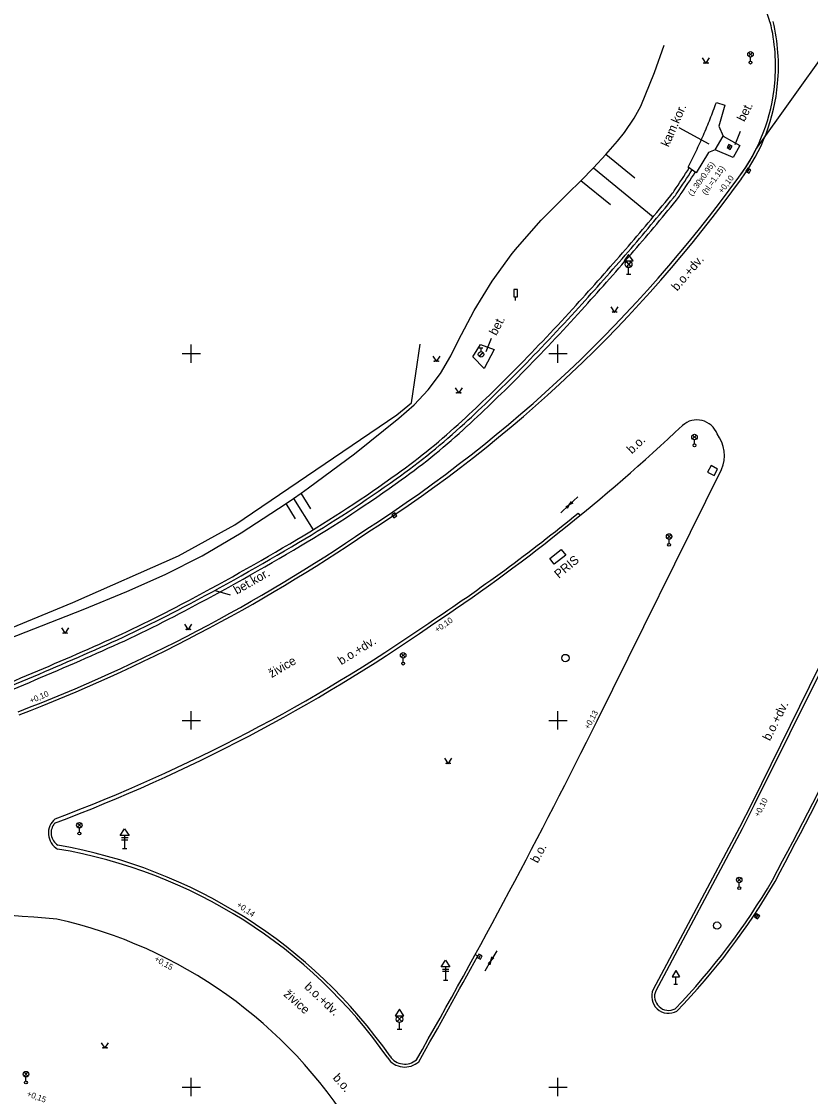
# Model space of a CAD drawing. Extents: x -599151 to -598424, y -1163476 to -1161924.
# Drawn here: x -598936.6 to -598882.8, y -1163175.6 to -1163102.4 of the extents above; entities that cross this region are included whole.
import ezdxf

# ---------------------------------------------------------------- set-up
doc = ezdxf.new("R2010")
doc.units = 0
for name, color, linetype in [('Vrstva 10', 7, 'Continuous'), ('Vrstva 14', 7, 'Continuous'), ('Vrstva 15', 7, 'Continuous'), ('Vrstva 19', 7, 'Continuous'), ('Vrstva 23', 7, 'Continuous'), ('Vrstva 24', 7, 'Continuous'), ('Vrstva 25', 7, 'Continuous'), ('Vrstva 29', 7, 'Continuous'), ('Vrstva 41', 7, 'Continuous'), ('Vrstva 44', 7, 'Continuous'), ('Vrstva 49', 7, 'Continuous'), ('Vrstva 50', 7, 'Continuous'), ('Vrstva 62', 7, 'Continuous'), ('Vrstva 63', 7, 'Continuous'), ('Vrstva 7', 7, 'Continuous')]:
    doc.layers.add(name, color=color, linetype=linetype)

msp = doc.modelspace()

# ---------------------------------------------------------------- linework, layer by layer
at = {"layer": 'Vrstva 10'}
msp.add_lwpolyline([(-598970.37, -1163152.041), (-598959.99, -1163150.901), (-598957.62, -1163150.501), (-598951.79, -1163148.951), (-598942, -1163145.641), (-598933.08, -1163141.961), (-598925.88, -1163138.781), (-598922.03, -1163136.681), (-598910.98, -1163129.171), (-598909.98, -1163128.361), (-598909.39, -1163124.361)], dxfattribs=at)
at = {"layer": 'Vrstva 14'}
for points in [[(-598890.156, -1163104.838), (-598889.906, -1163105.213), (-598889.656, -1163104.838)], [(-598896.392, -1163121.814), (-598896.142, -1163122.189), (-598895.892, -1163121.814)], [(-598908.54, -1163125.165), (-598908.29, -1163125.54), (-598908.04, -1163125.165)], [(-598907.013, -1163127.327), (-598906.763, -1163127.702), (-598906.513, -1163127.327)], [(-598933.85, -1163143.699), (-598933.6, -1163144.074), (-598933.35, -1163143.699)], [(-598925.45, -1163143.445), (-598925.2, -1163143.82), (-598924.95, -1163143.445)], [(-598907.73, -1163152.577), (-598907.48, -1163152.952), (-598907.23, -1163152.577)], [(-598931.131, -1163171.975), (-598930.881, -1163172.35), (-598930.631, -1163171.975)]]:
    msp.add_lwpolyline(points, dxfattribs=at)
for centre in [(-598890.031, -1163105.188), (-598889.781, -1163105.188), (-598896.267, -1163122.164), (-598896.017, -1163122.164), (-598908.415, -1163125.515), (-598908.165, -1163125.515), (-598906.888, -1163127.677), (-598906.638, -1163127.677), (-598933.725, -1163144.049), (-598933.475, -1163144.049), (-598925.325, -1163143.795), (-598925.075, -1163143.795), (-598907.605, -1163152.927), (-598907.355, -1163152.927), (-598931.006, -1163172.325), (-598930.756, -1163172.325)]:
    msp.add_circle(centre, 0.025, dxfattribs=at)
at = {"layer": 'Vrstva 15'}
msp.add_line((-598902.89, -1163121.39), (-598902.89, -1163121.14), dxfattribs=at)
msp.add_lwpolyline([(-598903.015, -1163121.14), (-598902.765, -1163121.14), (-598902.765, -1163120.64), (-598903.015, -1163120.64)], close=True, dxfattribs=at)
at = {"layer": 'Vrstva 19'}
for p, q in [((-598891.97, -1163167.057), (-598892.22, -1163167.49)), ((-598892.22, -1163167.49), (-598891.72, -1163167.49)), ((-598891.97, -1163167.057), (-598891.72, -1163167.49)), ((-598891.97, -1163167.99), (-598891.97, -1163167.49)), ((-598892.095, -1163167.99), (-598891.845, -1163167.99))]:
    msp.add_line(p, q, dxfattribs=at)
at = {"layer": 'Vrstva 23'}
for p, q in [((-598889.563, -1163132.632), (-598889.798, -1163133.073)), ((-598889.798, -1163133.073), (-598889.357, -1163133.308)), ((-598889.122, -1163132.867), (-598889.563, -1163132.632)), ((-598889.357, -1163133.308), (-598889.122, -1163132.867))]:
    msp.add_line(p, q, dxfattribs=at)
at = {"layer": 'Vrstva 24'}
for p, q in [((-598905.387, -1163125.166), (-598905.092, -1163124.934)), ((-598905.365, -1163124.612), (-598905.115, -1163124.612)), ((-598905.24, -1163124.862), (-598905.24, -1163124.612))]:
    msp.add_line(p, q, dxfattribs=at)
msp.add_circle((-598905.24, -1163125.05), 0.188, dxfattribs=at)
at = {"layer": 'Vrstva 25'}
for p, q in [((-598888.365, -1163111.018), (-598888.235, -1163110.804)), ((-598887.075, -1163112.627), (-598886.945, -1163112.413)), ((-598911.264, -1163136.09), (-598911.056, -1163135.95)), ((-598886.491, -1163163.463), (-598886.349, -1163163.257)), ((-598905.399, -1163166.22), (-598905.281, -1163166))]:
    msp.add_line(p, q, dxfattribs=at)
for points in [[(-598888.258, -1163111.083), (-598888.128, -1163110.869), (-598888.342, -1163110.739), (-598888.472, -1163110.953)], [(-598886.968, -1163112.692), (-598886.838, -1163112.478), (-598887.052, -1163112.348), (-598887.182, -1163112.562)], [(-598911.194, -1163136.194), (-598910.986, -1163136.054), (-598911.126, -1163135.846), (-598911.334, -1163135.986)], [(-598886.387, -1163163.534), (-598886.246, -1163163.327), (-598886.453, -1163163.186), (-598886.594, -1163163.393)], [(-598905.288, -1163166.279), (-598905.171, -1163166.058), (-598905.392, -1163165.941), (-598905.509, -1163166.162)]]:
    msp.add_lwpolyline(points, close=True, dxfattribs=at)
for centre in [(-598899.49, -1163145.75), (-598889.15, -1163163.99)]:
    msp.add_circle(centre, 0.25, dxfattribs=at)
at = {"layer": 'Vrstva 29'}
for p, q in [((-598887.002, -1163104.73), (-598886.738, -1163104.466)), ((-598886.734, -1163104.729), (-598886.998, -1163104.464)), ((-598886.87, -1163105.061), (-598886.87, -1163104.786)), ((-598890.822, -1163130.819), (-598890.558, -1163130.555)), ((-598890.554, -1163130.818), (-598890.818, -1163130.553)), ((-598890.69, -1163131.15), (-598890.69, -1163130.875)), ((-598892.552, -1163137.599), (-598892.288, -1163137.335)), ((-598892.284, -1163137.598), (-598892.548, -1163137.333)), ((-598892.42, -1163137.93), (-598892.42, -1163137.655)), ((-598910.682, -1163145.699), (-598910.418, -1163145.435)), ((-598910.414, -1163145.698), (-598910.678, -1163145.433)), ((-598910.55, -1163146.03), (-598910.55, -1163145.755)), ((-598932.762, -1163157.279), (-598932.498, -1163157.015)), ((-598932.494, -1163157.278), (-598932.758, -1163157.013)), ((-598932.63, -1163157.61), (-598932.63, -1163157.335)), ((-598887.772, -1163161.009), (-598887.508, -1163160.745)), ((-598887.504, -1163161.008), (-598887.768, -1163160.743)), ((-598887.64, -1163161.34), (-598887.64, -1163161.065)), ((-598936.402, -1163174.249), (-598936.138, -1163173.985)), ((-598936.134, -1163174.248), (-598936.398, -1163173.983)), ((-598936.27, -1163174.58), (-598936.27, -1163174.305))]:
    msp.add_line(p, q, dxfattribs=at)
msp.add_lwpolyline([(-598900.557, -1163138.964), (-598899.773, -1163138.344), (-598899.463, -1163138.736), (-598900.247, -1163139.356)], close=True, dxfattribs=at)
for centre, radius in [((-598886.87, -1163104.599), 0.188), ((-598886.87, -1163105.161), 0.1), ((-598890.69, -1163130.688), 0.188), ((-598890.69, -1163131.25), 0.1), ((-598892.42, -1163137.468), 0.188), ((-598892.42, -1163138.03), 0.1), ((-598910.55, -1163145.568), 0.188), ((-598910.55, -1163146.13), 0.1), ((-598932.63, -1163157.147), 0.188), ((-598932.63, -1163157.71), 0.1), ((-598887.64, -1163160.877), 0.188), ((-598887.64, -1163161.44), 0.1), ((-598936.27, -1163174.117), 0.188), ((-598936.27, -1163174.68), 0.1)]:
    msp.add_circle(centre, radius, dxfattribs=at)
at = {"layer": 'Vrstva 41'}
for points in [[(-598895.941, -1163110.509), (-598895.46, -1163109.92), (-598894.795, -1163108.961), (-598894.357, -1163108.125), (-598893.411, -1163105.847), (-598892.76, -1163103.98)], [(-598896.74, -1163111.437), (-598895.941, -1163110.509)], [(-598897.569, -1163112.342), (-598896.74, -1163111.437)], [(-598894.76, -1163113.045), (-598896.74, -1163111.437)], [(-598898.429, -1163113.222), (-598897.569, -1163112.342)], [(-598897.569, -1163112.342), (-598893.497, -1163115.665)], [(-598899.32, -1163114.077), (-598898.429, -1163113.222)], [(-598896.425, -1163114.865), (-598898.429, -1163113.222)], [(-598917.004, -1163134.158), (-598913.879, -1163131.837), (-598910.852, -1163129.39), (-598909.8, -1163128.49), (-598908.839, -1163127.472), (-598908, -1163126.352), (-598907.295, -1163125.143), (-598906.811, -1163124.132), (-598905.714, -1163122.062), (-598904.478, -1163120.071), (-598903.11, -1163118.17), (-598902.765, -1163117.743), (-598901.152, -1163115.903), (-598899.32, -1163114.077)], [(-598918.019, -1163134.87), (-598917.51, -1163134.515)], [(-598917.51, -1163134.515), (-598917.004, -1163134.158)], [(-598916.851, -1163135.582), (-598917.51, -1163134.515)], [(-598919.042, -1163135.568), (-598918.53, -1163135.221)], [(-598918.53, -1163135.221), (-598918.019, -1163134.87)], [(-598917.889, -1163136.26), (-598918.53, -1163135.221)], [(-598918.019, -1163134.87), (-598916.697, -1163137.01)], [(-598962.571, -1163152.267), (-598959.703, -1163151.72), (-598958.21, -1163151.37), (-598953.982, -1163150.231), (-598949.798, -1163148.938), (-598945.902, -1163147.581), (-598939.112, -1163145.084), (-598932.379, -1163142.438), (-598929.387, -1163141.206), (-598926.789, -1163140.066), (-598924.26, -1163138.782), (-598921.599, -1163137.228), (-598919.042, -1163135.568)]]:
    msp.add_lwpolyline(points, dxfattribs=at)
for centre, radius, start, end in [((-598959.289, -1163068.731), 81.228, 326.0972, 327.41255), ((-598895.702, -1163111.464), 4.617, 320.74636, 326.0972), ((-599028.927, -1163002.6), 176.664, 319.19091, 320.74636), ((-599044.871, -1162988.833), 197.728, 317.72064, 319.19091), ((-599007.526, -1163022.79), 147.253, 315.40117, 317.72064), ((-598980.944, -1163049.001), 109.922, 312.71655, 315.40117), ((-598938.242, -1163095.251), 46.969, 305.39357, 312.71655), ((-598966.367, -1163056.112), 95.165, 300.77255, 305.54898), ((-599006.454, -1162988.791), 173.517, 297.79088, 300.77256), ((-598969.509, -1163058.89), 94.279, 293.74558, 297.79088), ((-599065.283, -1162841.183), 332.12, 292.5952, 293.74558)]:
    msp.add_arc(centre, radius, start, end, dxfattribs=at)
at = {"layer": 'Vrstva 44'}
for p, q in [((-598895.03, -1163118.74), (-598895.33, -1163119.084)), ((-598895.33, -1163118.74), (-598895.03, -1163119.084)), ((-598895.18, -1163119.59), (-598895.18, -1163119.14)), ((-598895.33, -1163119.59), (-598895.03, -1163119.59)), ((-598929.76, -1163157.99), (-598929.312, -1163157.99)), ((-598929.54, -1163157.84), (-598929.54, -1163158.74)), ((-598929.76, -1163158.14), (-598929.317, -1163158.14)), ((-598929.69, -1163158.74), (-598929.39, -1163158.74)), ((-598907.66, -1163166.8), (-598907.66, -1163167.7)), ((-598907.88, -1163166.95), (-598907.432, -1163166.95)), ((-598907.88, -1163167.1), (-598907.437, -1163167.1)), ((-598907.81, -1163167.7), (-598907.51, -1163167.7)), ((-598910.65, -1163170.19), (-598910.95, -1163170.534)), ((-598910.95, -1163170.19), (-598910.65, -1163170.534)), ((-598910.95, -1163171.04), (-598910.65, -1163171.04)), ((-598910.8, -1163171.04), (-598910.8, -1163170.59))]:
    msp.add_line(p, q, dxfattribs=at)
for points in [[(-598895.48, -1163118.684), (-598894.88, -1163118.684), (-598895.18, -1163118.234), (-598895.48, -1163118.684)], [(-598911.1, -1163170.134), (-598910.5, -1163170.134), (-598910.8, -1163169.684), (-598911.1, -1163170.134)]]:
    msp.add_lwpolyline(points, dxfattribs=at)
for points in [[(-598929.84, -1163157.845), (-598929.54, -1163157.39), (-598929.24, -1163157.845)], [(-598907.96, -1163166.805), (-598907.66, -1163166.35), (-598907.36, -1163166.805)]]:
    msp.add_lwpolyline(points, close=True, dxfattribs=at)
for centre in [(-598895.18, -1163118.912), (-598910.8, -1163170.362)]:
    msp.add_circle(centre, 0.228, dxfattribs=at)
at = {"layer": 'Vrstva 49'}
for p, q in [((-598889.691, -1163110.717), (-598891.735, -1163109.609)), ((-598899.8, -1163135.862), (-598899.224, -1163135.318)), ((-598899.469, -1163135.451), (-598899.224, -1163135.318)), ((-598899.224, -1163135.318), (-598899.37, -1163135.557)), ((-598898.648, -1163134.773), (-598899.224, -1163135.318)), ((-598899.224, -1163135.318), (-598899.078, -1163135.079)), ((-598898.979, -1163135.184), (-598899.224, -1163135.318)), ((-598923.374, -1163141.158), (-598922.337, -1163141.446)), ((-598904.169, -1163165.7), (-598904.568, -1163166.385)), ((-598904.568, -1163166.385), (-598904.496, -1163166.114)), ((-598904.967, -1163167.069), (-598904.568, -1163166.385)), ((-598904.766, -1163166.581), (-598904.568, -1163166.385)), ((-598904.568, -1163166.385), (-598904.641, -1163166.655)), ((-598904.371, -1163166.188), (-598904.568, -1163166.385))]:
    msp.add_line(p, q, dxfattribs=at)
for points in [[(-598887.909, -1163110.739), (-598887.547, -1163109.835)], [(-598904.89, -1163124.851), (-598904.528, -1163123.947)]]:
    msp.add_lwpolyline(points, dxfattribs=at)
at = {"layer": 'Vrstva 62'}
for p, q in [((-598925.625, -1163125), (-598924.375, -1163125)), ((-598925, -1163125.625), (-598925, -1163124.375)), ((-598900.625, -1163125), (-598899.375, -1163125)), ((-598900, -1163125.625), (-598900, -1163124.375)), ((-598925.625, -1163150), (-598924.375, -1163150)), ((-598925, -1163150.625), (-598925, -1163149.375)), ((-598900.625, -1163150), (-598899.375, -1163150)), ((-598900, -1163150.625), (-598900, -1163149.375)), ((-598925, -1163175.625), (-598925, -1163174.375)), ((-598900, -1163175.625), (-598900, -1163174.375)), ((-598925.625, -1163175), (-598924.375, -1163175)), ((-598900.625, -1163175), (-598899.375, -1163175))]:
    msp.add_line(p, q, dxfattribs=at)
at = {"layer": 'Vrstva 63'}
for points in [[(-598886.501, -1163111.085), (-598879.25, -1163100.96)], [(-598897.33, -1163150.03), (-598888.84, -1163132.9)], [(-598875.4, -1163136.75), (-598879.4, -1163141.23), (-598886.61, -1163155.75), (-598887.45, -1163157.39), (-598893.33, -1163168.43)]]:
    msp.add_lwpolyline(points, dxfattribs=at)
for centre, radius, start, end in [((-598897.754, -1163105.453), 12.584, 323.25937, 333.41058), ((-598964.192, -1163057.404), 94.575, 302.69951, 324.01014), ((-598980.673, -1163035.451), 129.886, 303.6608, 313.35722), ((-598890.523, -1163130.984), 1.467, 20.52491, 131.74706), ((-598891.138, -1163131.958), 2.483, 337.71712, 36.82302), ((-598977.73, -1163042.484), 114.492, 290.94636, 304.36727), ((-599361.191, -1162908.944), 538.407, 332.0989, 334.61954), ((-598976.086, -1163046.255), 118.372, 290.66391, 304.71172), ((-599302.271, -1162948.994), 452.098, 330.27808, 333.59753), ((-598933.553, -1163157.663), 1.002, 139.43568, 237.62805), ((-598940.082, -1163192.962), 34.969, 35.00883, 80.13394), ((-598925.305, -1163137.553), 46.254, 316.04041, 329.69893), ((-598944.061, -1163271.589), 108.492, 84.76397, 98.10136), ((-598941.11, -1163194.732), 31.947, 31.6672, 77.43438), ((-598892.453, -1163168.812), 0.957, 156.4477, 297.59501), ((-598910.439, -1163172.227), 1.206, 213.90675, 310.8201)]:
    msp.add_arc(centre, radius, start, end, dxfattribs=at)
at = {"layer": 'Vrstva 7'}
for p, q in [((-598889.28, -1163111.111), (-598888.74, -1163110.171)), ((-598897.33, -1163150.03), (-598888.84, -1163132.9)), ((-598898.627, -1163135.885), (-598898.5, -1163136.04)), ((-598905.632, -1163165.95), (-598905.456, -1163166.046))]:
    msp.add_line(p, q, dxfattribs=at)
for points in [[(-598889.2, -1163107.881), (-598888.63, -1163108.061), (-598889.04, -1163109.491), (-598888.74, -1163110.171), (-598887.6, -1163110.811), (-598888.05, -1163111.641), (-598889.28, -1163111.111), (-598889.73, -1163111.281), (-598890.57, -1163112.681), (-598891.12, -1163112.281)], [(-598905.03, -1163126.021), (-598905.81, -1163125.211), (-598905.28, -1163124.371), (-598904.35, -1163124.711), (-598905.03, -1163126.021)], [(-598879.61, -1163141.11), (-598886.789, -1163155.66), (-598887.627, -1163157.297), (-598893.508, -1163168.337)], [(-598879.4, -1163141.23), (-598886.61, -1163155.75), (-598887.45, -1163157.39), (-598893.33, -1163168.43)]]:
    msp.add_lwpolyline(points, dxfattribs=at)
for centre, radius, start, end in [((-598896.545, -1163105.653), 11.466, 16.3906, 21.87436), ((-598897.984, -1163105.4), 13.018, 354.76232, 13.48833), ((-598897.984, -1163105.4), 12.818, 354.76121, 13.48833), ((-598897.754, -1163105.453), 12.584, 323.25937, 354.90539), ((-598897.754, -1163105.453), 12.784, 323.25937, 354.90426), ((-598922.59, -1163095.929), 35.464, 338.3768, 340.30624), ((-598922.59, -1163095.929), 35.464, 336.44737, 338.3768), ((-598922.59, -1163095.929), 35.464, 334.49586, 336.44737), ((-598922.59, -1163095.929), 35.464, 332.54435, 334.49586), ((-598959.288, -1163068.731), 80.987, 326.0972, 327.42321), ((-598964.192, -1163057.404), 94.575, 302.69951, 324.01014), ((-598963.449, -1163058.289), 93.664, 302.61874, 324.19127), ((-598959.288, -1163068.731), 81.487, 326.0972, 327.40201), ((-598895.702, -1163111.463), 4.376, 320.74636, 326.0972), ((-599028.927, -1163002.599), 176.424, 319.19091, 320.74636), ((-599028.927, -1163002.599), 176.924, 319.19091, 320.74636), ((-598895.702, -1163111.463), 4.876, 320.74636, 326.0972), ((-599044.871, -1162988.833), 197.488, 317.72064, 319.19091), ((-599044.871, -1162988.833), 197.988, 317.72064, 319.19091), ((-599007.526, -1163022.79), 147.013, 315.40117, 317.72064), ((-599007.526, -1163022.79), 147.513, 315.40117, 317.72064), ((-598980.944, -1163049.002), 109.682, 312.71655, 315.40117), ((-598980.944, -1163049.002), 110.182, 312.71655, 315.40117), ((-598938.242, -1163095.251), 46.733, 305.70042, 312.71655), ((-598938.242, -1163095.251), 47.233, 305.70042, 312.71655), ((-598980.673, -1163035.451), 129.886, 303.6608, 313.35722), ((-598890.523, -1163130.984), 1.467, 20.52491, 131.74706), ((-598891.138, -1163131.958), 2.483, 337.71712, 36.82302), ((-598966.366, -1163056.112), 94.929, 300.77255, 305.70042), ((-598966.366, -1163056.112), 95.429, 300.77255, 305.70042), ((-598980.441, -1163035.243), 129.701, 303.52341, 309.10849), ((-598977.73, -1163042.484), 114.492, 290.94636, 304.36727), ((-598979.155, -1163039.68), 117.847, 291.09498, 304.17356), ((-599006.454, -1162988.791), 173.281, 297.79088, 300.77256), ((-599006.454, -1162988.791), 173.781, 297.79088, 300.77256), ((-599361.191, -1162908.944), 538.407, 332.0989, 334.61954), ((-599360.862, -1162908.74), 538.412, 332.06286, 334.58394), ((-598969.509, -1163058.89), 94.043, 293.74558, 297.79088), ((-598969.509, -1163058.89), 94.543, 293.74558, 297.79088), ((-598975.335, -1163047.318), 116.84, 290.56905, 304.70622), ((-598976.086, -1163046.255), 118.372, 290.66391, 304.71172), ((-599065.283, -1162841.183), 331.885, 292.5952, 293.74558), ((-599065.283, -1162841.183), 332.385, 292.5952, 293.74558), ((-599386.517, -1162899.53), 577.281, 330.762706, 334.813631), ((-599302.271, -1162948.994), 452.098, 330.27808, 333.59753), ((-598933.478, -1163157.679), 1.261, 129.77671, 239.92641), ((-598933.553, -1163157.663), 1.002, 139.43568, 237.62805), ((-598939.829, -1163192.708), 34.416, 34.9093, 80.4341), ((-598940.082, -1163192.962), 34.969, 35.00883, 80.13394), ((-598925.305, -1163137.553), 46.254, 316.04041, 329.69892), ((-598925.305, -1163137.553), 46.454, 316.00226, 329.70409), ((-598944.061, -1163271.589), 108.492, 84.76397, 98.10136), ((-599422.302, -1162879.86), 617.881, 328.758636, 332.714644), ((-598941.11, -1163194.732), 31.947, 31.6672, 77.43437), ((-599302.271, -1162948.994), 452.298, 330.27391, 331.32192), ((-598892.453, -1163168.812), 1.157, 155.74349, 299.27636), ((-598892.453, -1163168.812), 0.957, 156.4477, 297.59503), ((-598910.439, -1163172.227), 1.406, 213.90675, 312.26884), ((-598910.439, -1163172.227), 1.206, 213.90675, 310.8201)]:
    msp.add_arc(centre, radius, start, end, dxfattribs=at)

# ---------------------------------------------------------------- texts
at = {"layer": 'Vrstva 49'}
for s, rotation, p in [('kam.kor.', 66.43633, (-598892.454, -1163110.956)), ('bet.', 62.98652, (-598887.293, -1163109.238)), ('b.o.+dv.', 49.42381, (-598891.873, -1163120.773)), ('bet.', 62.98652, (-598904.197, -1163123.813)), ('b.o.', 43.59785, (-598894.958, -1163131.871)), ('PRIS', 39.87036, (-598899.938, -1163140.361)), ('bet.kor.', 29.67784, (-598921.898, -1163141.437)), ('b.o.+dv.', 31.78539, (-598914.773, -1163146.248)), ('živice', 30.52757, (-598919.516, -1163147.122)), ('b.o.+dv.', 63.59301, (-598885.542, -1163151.441)), ('b.o.', 61.88272, (-598901.38, -1163159.777)), ('živice', 318.43756, (-598918.749, -1163168.734)), ('b.o.+dv.', 316.75996, (-598917.335, -1163168.217)), ('b.o.', 311.66325, (-598915.385, -1163174.397))]:
    msp.add_text(s, height=0.6, rotation=rotation, dxfattribs=at).set_placement(p)
at = {"layer": 'Vrstva 50'}
for s, rotation, p in [('(1.30x0.95)', 54.38878, (-598890.845, -1163114.297)), ('(hl.=1.15)', 54.38878, (-598889.903, -1163114.222)), ('+0,10', 53.28565, (-598888.787, -1163114.117)), ('+0,10', 34.77935, (-598908.235, -1163144.038)), ('+0,10', 23.33178, (-598935.919, -1163148.865)), ('+0,13', 61.70827, (-598897.885, -1163150.65)), ('+0,10', 63.15016, (-598886.288, -1163156.622)), ('+0,14', 325.42684, (-598921.944, -1163162.666)), ('+0,15', 330.19207, (-598927.555, -1163166.373)), ('+0,15', 340.06587, (-598936.249, -1163175.609))]:
    msp.add_text(s, height=0.4, rotation=rotation, dxfattribs=at).set_placement(p)

doc.saveas('drawing.dxf')
